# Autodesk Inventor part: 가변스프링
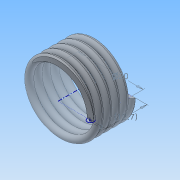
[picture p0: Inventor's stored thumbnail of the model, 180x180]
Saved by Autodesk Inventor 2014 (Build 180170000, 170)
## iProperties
Created: 2020-06
Part Number: 가변스프링
Material: 일반
Document SubType Name: Modeling
Designer: NET
Density: 1 g/cm^3
Appearance: 기본값
Mass: 0.953965 g
Surface Area: 19.5658 cm^2
Volume: 0.953965 cm^3
Author: NET
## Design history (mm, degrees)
sketch "스케치1"
  geometry: L1 (0, 0)-(10, 0); L2 (10, 0)-(10, 12.7); L3 (10, 12.7)-(0, 12.7); L4 (0, 12.7)-(0, 0); C1 r 1 at (10, 0)
  constraints: 8 end point, 2 parallel, 1 centre point, 1 coincident, 1 horizontal, 1 perpendicular
  dimensions: "d0" = 2 diameter of C1; "d1" = 12.7 distance of L1.end L2.end (derived); "d2" = 20 diameter of L2 L4
feature "코일1" sketch "스케치1" pitch "d3" = 10; turns "d5" = 5; dims "d4" = 12.7 (= d1), "d6" = 0, angle "d7" = 90 deg, angle "d8" = 90 deg, "d9" = 0, "d10" = 0
node "작업 평면1"
sketch "스케치2"
  geometry: L1 (-11, 0)-(-9, 0) reference; 1 further point
  constraints: 1 horizontal alignment
extrude "돌출1" cut sketch "스케치2" distance "d11" = 10; taper "d12" = 0 deg
node "작업 평면2"
sketch "스케치3"
  geometry: L1 (11, 0)-(9, 0) reference; 1 further point
  constraints: 1 horizontal alignment
extrude "돌출2" cut sketch "스케치3" distance "d13" = 10; taper "d14" = 0 deg
node "솔리드1"
node "절단 모서리 투영1"
node "절단 모서리 투영2"
